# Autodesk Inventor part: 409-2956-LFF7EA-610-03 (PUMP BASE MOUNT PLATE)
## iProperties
Created: 2011-01
Part Number: 409-2956-LFF7EA-610-03 (PUMP BASE MOUNT PLATE)
Cost Center: 0 lbmass
Material: A36 STEEL PLATE
Document SubType Name: Sheet Metal
Designer: S. Boerckel
Authority: 0 in^3
Mass: 2841.15 g
Surface Area: 700.573 cm^2
Volume: 361.469 cm^3
Density: 7.86 g/cm^3
Flat Pattern Width: 7.62 cm
Flat Pattern Length: 38.1 cm
Flat Pattern Area: 290.322 cm^2
Sheet Metal Rule: 1/2"Thk
Description: TOP MOUNT PLATE
SaveDate: 2008-01-15
SaveTime: 10:24
FileName: Sheet Metal
Wide: =<Flat Pattern Width>cm
Length: =<Flat Pattern Length>cm
Thickness: 0.5000 in
SMR: =<Sheet Metal Rule> - <Material>
Author: S. Boerckel
Revision Number: 0
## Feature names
1. Hole1
2. Plate1
